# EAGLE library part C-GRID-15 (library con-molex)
CONNECTOR wire to board 2.54 mm (0.100") pitch header
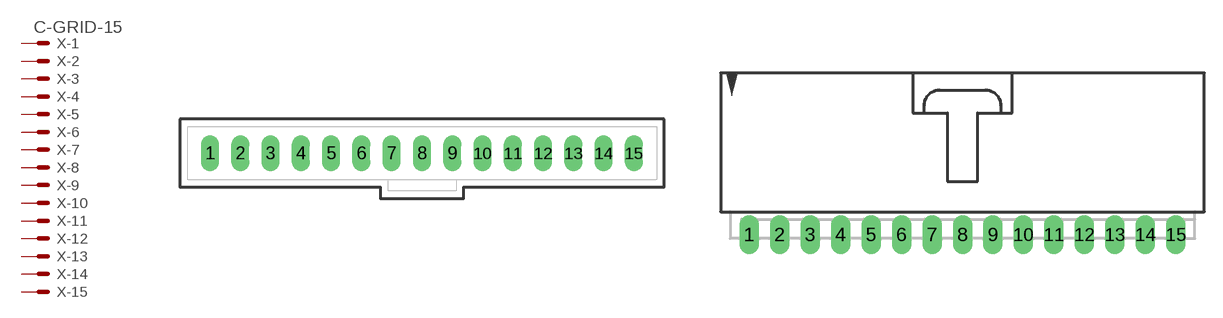
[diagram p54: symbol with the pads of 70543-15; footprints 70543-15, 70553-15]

Designator prefix X; gates -1=MV -2=M -3=M -4=M -5=M -6=M -7=M -8=M -9=M -10=M -11=M -12=M -13=M -14=M -15=M

## C-GRID-15-70543 (OC_FARNELL: unknown; OC_NEWARK: unknown)  [70543-15]
1  -1:S  pas
2  -2:S  pas
3  -3:S  pas
4  -4:S  pas
5  -5:S  pas
6  -6:S  pas
7  -7:S  pas
8  -8:S  pas
9  -9:S  pas
10  -10:S  pas
11  -11:S  pas
12  -12:S  pas
13  -13:S  pas
14  -14:S  pas
15  -15:S  pas

## C-GRID-15-70553 (OC_FARNELL: unknown; OC_NEWARK: unknown)  [70553-15]
Pads as for 70543-15

## C-GRID-15-74099 (OC_FARNELL: unknown; OC_NEWARK: unknown)  [74099-15]
Pads as for 70543-15

## C-GRID-15-15-91 (OC_FARNELL: unknown; OC_NEWARK: unknown)  [15-91-15]
Pads as for 70543-15

## Footprint 70543-15 (pad centres in mm)
C-Grid SL Connector vertical, 15 pin
drill 1.016 long: 1 -17.78,0; 2 -15.24,0; 3 -12.7,0; 4 -10.16,0; 5 -7.62,0; 6 -5.08,0; 7 -2.54,0; 8 0,0; 9 2.54,0; 10 5.08,0; 11 7.62,0; 12 10.16,0; 13 12.7,0; 14 15.24,0; 15 17.78,0

## Footprint 70553-15 (pad centres in mm)
C-Grid SL Connector right angle, 15 pin
drill 1.092 long: 1 -17.78,-7.62; 2 -15.24,-7.62; 3 -12.7,-7.62; 4 -10.16,-7.62; 5 -7.62,-7.62; 6 -5.08,-7.62; 7 -2.54,-7.62; 8 0,-7.62; 9 2.54,-7.62; 10 5.08,-7.62; 11 7.62,-7.62; 12 10.16,-7.62; 13 12.7,-7.62; 14 15.24,-7.62; 15 17.78,-7.62

## Footprint 74099-15 (pad centres in mm)
C-Grid SL Connector vertical SMD, 15 pin
smd 1.27 x 3.175: 1 -17.78,-2.223; 2 -15.24,2.223; 3 -12.7,-2.223; 4 -10.16,2.223; 5 -7.62,-2.223; 6 -5.08,2.223; 7 -2.54,-2.223; 8 0,2.223; 9 2.54,-2.223; 10 5.08,2.223; 11 7.62,-2.223; 12 10.16,2.223; 13 12.7,-2.223; 14 15.24,2.223; 15 17.78,-2.223

## Footprint 15-91-15 (pad centres in mm)
C-Grid SL Connector right angle SMD, 15 pin
smd 1.651 x 5.334: 1 -17.78,-10.795; 2 -15.24,-10.795; 3 -12.7,-10.795; 4 -10.16,-10.795; 5 -7.62,-10.795; 6 -5.08,-10.795; 7 -2.54,-10.795; 8 0,-10.795; 9 2.54,-10.795; 10 5.08,-10.795; 11 7.62,-10.795; 12 10.16,-10.795; 13 12.7,-10.795; 14 15.24,-10.795; 15 17.78,-10.795
hole 3.404 at -19.177,0.838
hole 3.404 at 19.177,0.838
